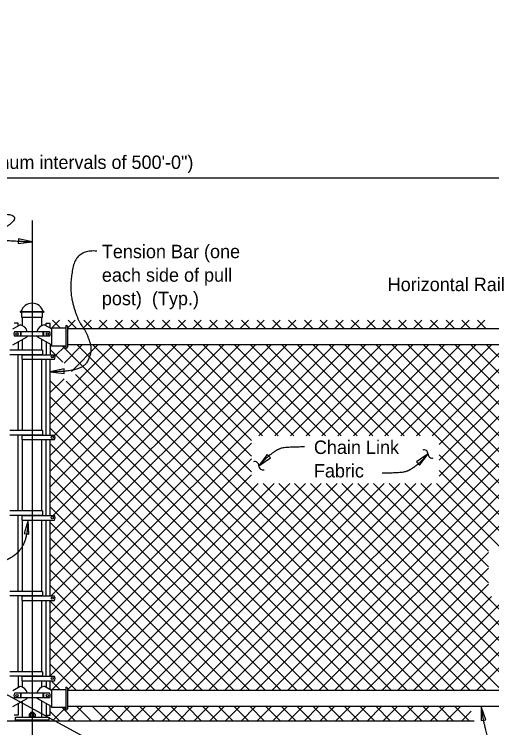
# Model space of a CAD drawing. Extents: x 110698 to 110915, y 110390 to 110472.
# Drawn here: x 110786.56 to 110793.7, y 110413.66 to 110424.35 of the extents above; entities that cross this region are included whole.
import ezdxf

# ---------------------------------------------------------------- set-up
doc = ezdxf.new("R2010")
doc.units = 0
for name, color, linetype in [('AdhocPoint_dp', 7, 'Continuous'), ('Border', 7, 'Continuous'), ('PlotBorder_dp', 7, 'Continuous'), ('SheetBorder_dp', 7, 'Continuous'), ('SheetLines_dp', 7, 'Continuous'), ('TextMisc', 7, 'Continuous')]:
    doc.layers.add(name, color=color, linetype=linetype)

msp = doc.modelspace()

# ---------------------------------------------------------------- linework, layer by layer
at = {"layer": 'AdhocPoint_dp'}
msp.add_line((110786.826, 110421.264), (110786.826, 110413.354), dxfattribs=at)
at = {"layer": 'PlotBorder_dp'}
for p, q in [((110776.826, 110421.899), (110796.826, 110421.899)), ((110786.826, 110413.828), (110786.826, 110413.827))]:
    msp.add_line(p, q, dxfattribs=at)
for points in [[(110786.826, 110420.942), (110786.62, 110420.989), (110786.616, 110420.919)], [(110787.096, 110418.997), (110787.306, 110418.971), (110787.303, 110419.041)], [(110792.751, 110417.764), (110792.576, 110417.646), (110792.625, 110417.595)], [(110790.219, 110417.588), (110790.394, 110417.706), (110790.346, 110417.757)], [(110786.768, 110416.774), (110786.708, 110416.572), (110786.778, 110416.563)], [(110793.547, 110413.981), (110793.548, 110413.77), (110793.618, 110413.783)]]:
    msp.add_lwpolyline(points, close=True, dxfattribs=at)
for centre, start, end in [((110792.691, 110417.766), 357.7178, 109.445), ((110792.81, 110417.762), 177.7178, 289.445), ((110790.16, 110417.59), 357.7178, 109.445), ((110790.279, 110417.585), 177.7178, 289.445)]:
    msp.add_arc(centre, 0.0596, start, end, dxfattribs=at)
for points in [[(110785.936, 110421.366), (110786.482, 110421.376), (110786.604, 110421.287), (110786.36, 110421.106), (110786.275, 110421.087), (110786.275, 110420.97), (110786.553, 110420.957), (110786.826, 110420.942)], [(110787.792, 110420.802), (110787.492, 110420.834), (110787.376, 110420.252), (110787.492, 110419.797), (110787.655, 110419.562), (110787.734, 110419.276), (110787.548, 110418.987), (110787.096, 110418.997)], [(110790.904, 110417.869), (110790.614, 110417.869), (110790.478, 110417.824), (110790.291, 110417.671), (110790.252, 110417.613)], [(110792.066, 110417.482), (110792.356, 110417.482), (110792.493, 110417.527), (110792.68, 110417.68), (110792.718, 110417.738)], [(110785.137, 110416.179), (110785.534, 110416.185), (110785.983, 110416.122), (110786.344, 110416.105), (110786.765, 110416.383), (110786.768, 110416.774)], [(110793.235, 110413.234), (110793.458, 110413.231), (110793.543, 110413.27), (110793.674, 110413.419), (110793.589, 110413.716), (110793.547, 110413.981)]]:
    msp.add_open_spline(points, degree=2, dxfattribs=at)
at = {"layer": 'SheetBorder_dp'}
for p, q in [((110787.122, 110419.653), (110787.237, 110419.768)), ((110787.129, 110419.768), (110787.244, 110419.653)), ((110787.355, 110419.651), (110787.472, 110419.768)), ((110787.365, 110419.768), (110787.495, 110419.638)), ((110787.578, 110419.638), (110787.708, 110419.768)), ((110787.6, 110419.768), (110787.731, 110419.638)), ((110787.813, 110419.638), (110787.944, 110419.768)), ((110787.836, 110419.768), (110787.966, 110419.638)), ((110788.049, 110419.638), (110788.179, 110419.768)), ((110788.072, 110419.768), (110788.202, 110419.638)), ((110788.285, 110419.638), (110788.415, 110419.768)), ((110788.308, 110419.768), (110788.438, 110419.638)), ((110788.521, 110419.638), (110788.651, 110419.768)), ((110788.543, 110419.768), (110788.673, 110419.638)), ((110788.756, 110419.638), (110788.886, 110419.768)), ((110788.779, 110419.768), (110788.909, 110419.638)), ((110788.992, 110419.638), (110789.122, 110419.768)), ((110789.015, 110419.768), (110789.145, 110419.638)), ((110789.228, 110419.638), (110789.358, 110419.768)), ((110789.25, 110419.768), (110789.381, 110419.638)), ((110789.463, 110419.638), (110789.594, 110419.768)), ((110789.486, 110419.768), (110789.616, 110419.638)), ((110789.699, 110419.638), (110789.829, 110419.768)), ((110789.722, 110419.768), (110789.852, 110419.638)), ((110789.935, 110419.638), (110790.065, 110419.768)), ((110789.958, 110419.768), (110790.088, 110419.638)), ((110790.17, 110419.638), (110790.301, 110419.768)), ((110790.193, 110419.768), (110790.323, 110419.638)), ((110790.406, 110419.638), (110790.536, 110419.768)), ((110790.429, 110419.768), (110790.559, 110419.638)), ((110790.642, 110419.638), (110790.772, 110419.768)), ((110790.665, 110419.768), (110790.795, 110419.638)), ((110790.878, 110419.638), (110791.008, 110419.768)), ((110790.9, 110419.768), (110791.03, 110419.638)), ((110791.113, 110419.638), (110791.243, 110419.768)), ((110791.136, 110419.768), (110791.266, 110419.638)), ((110791.349, 110419.638), (110791.479, 110419.768)), ((110791.372, 110419.768), (110791.502, 110419.638)), ((110791.585, 110419.638), (110791.715, 110419.768)), ((110791.607, 110419.768), (110791.738, 110419.638)), ((110791.82, 110419.638), (110791.951, 110419.768)), ((110791.843, 110419.768), (110791.973, 110419.638)), ((110792.056, 110419.638), (110792.186, 110419.768)), ((110792.079, 110419.768), (110792.209, 110419.638)), ((110792.292, 110419.638), (110792.422, 110419.768)), ((110792.315, 110419.768), (110792.445, 110419.638)), ((110792.528, 110419.638), (110792.658, 110419.768)), ((110792.55, 110419.768), (110792.68, 110419.638)), ((110792.763, 110419.638), (110792.893, 110419.768)), ((110792.786, 110419.768), (110792.916, 110419.638)), ((110792.999, 110419.638), (110793.129, 110419.768)), ((110793.022, 110419.768), (110793.152, 110419.638)), ((110793.235, 110419.638), (110793.365, 110419.768)), ((110793.257, 110419.768), (110793.388, 110419.638)), ((110793.47, 110419.638), (110793.6, 110419.768)), ((110793.493, 110419.768), (110793.623, 110419.638)), ((110787.096, 110416.328), (110790.167, 110419.398)), ((110787.096, 110415.857), (110790.638, 110419.398)), ((110787.096, 110417.742), (110788.752, 110419.398)), ((110787.096, 110417.271), (110789.224, 110419.398)), ((110787.096, 110418.214), (110788.281, 110419.398)), ((110787.096, 110416.092), (110790.402, 110419.398)), ((110787.096, 110416.564), (110789.931, 110419.398)), ((110787.096, 110417.035), (110789.46, 110419.398)), ((110787.096, 110417.506), (110788.988, 110419.398)), ((110787.096, 110415.149), (110791.345, 110419.398)), ((110787.096, 110415.385), (110791.109, 110419.398)), ((110787.096, 110418.449), (110788.045, 110419.398)), ((110787.113, 110415.637), (110790.874, 110419.398)), ((110787.139, 110416.842), (110789.695, 110419.398)), ((110787.162, 110418.044), (110788.517, 110419.398)), ((110787.168, 110419.228), (110787.328, 110419.388)), ((110787.28, 110419.381), (110792.44, 110414.221)), ((110787.303, 110419.127), (110787.574, 110419.398)), ((110787.414, 110419.002), (110787.81, 110419.398)), ((110787.499, 110419.398), (110792.676, 110414.221)), ((110787.735, 110419.398), (110792.912, 110414.221)), ((110787.97, 110419.398), (110793.147, 110414.221)), ((110788.206, 110419.398), (110790.108, 110417.496)), ((110788.442, 110419.398), (110790.108, 110417.732)), ((110788.677, 110419.398), (110790.108, 110417.967)), ((110788.913, 110419.398), (110790.274, 110418.038)), ((110789.149, 110419.398), (110790.509, 110418.038)), ((110789.384, 110419.398), (110790.745, 110418.038)), ((110789.62, 110419.398), (110790.981, 110418.038)), ((110789.856, 110419.398), (110791.216, 110418.038)), ((110789.939, 110414.221), (110795.116, 110419.398)), ((110790.092, 110419.398), (110791.452, 110418.038)), ((110790.175, 110414.221), (110795.352, 110419.398)), ((110790.22, 110418.038), (110791.581, 110419.398)), ((110790.327, 110419.398), (110791.688, 110418.038)), ((110790.411, 110414.221), (110795.588, 110419.398)), ((110790.456, 110418.038), (110791.817, 110419.398)), ((110790.563, 110419.398), (110791.923, 110418.038)), ((110790.646, 110414.221), (110795.823, 110419.398)), ((110790.692, 110418.038), (110792.052, 110419.398)), ((110790.799, 110419.398), (110792.159, 110418.038)), ((110790.882, 110414.221), (110796.059, 110419.398)), ((110790.927, 110418.038), (110792.288, 110419.398)), ((110791.034, 110419.398), (110792.395, 110418.038)), ((110791.118, 110414.221), (110796.296, 110419.399)), ((110791.163, 110418.038), (110792.524, 110419.398)), ((110791.27, 110419.398), (110792.631, 110418.038)), ((110791.353, 110414.221), (110796.513, 110419.381)), ((110791.399, 110418.038), (110792.759, 110419.398)), ((110791.506, 110419.398), (110794.532, 110416.372)), ((110791.635, 110418.038), (110792.995, 110419.398)), ((110791.741, 110419.398), (110794.767, 110416.372)), ((110791.87, 110418.038), (110793.231, 110419.398)), ((110791.977, 110419.398), (110795.003, 110416.372)), ((110792.106, 110418.038), (110793.466, 110419.398)), ((110792.213, 110419.398), (110795.239, 110416.372)), ((110792.342, 110418.038), (110793.702, 110419.398)), ((110792.449, 110419.398), (110795.474, 110416.372)), ((110792.577, 110418.038), (110793.938, 110419.398)), ((110792.684, 110419.398), (110795.71, 110416.372)), ((110792.813, 110418.038), (110794.174, 110419.398)), ((110792.916, 110417.905), (110794.409, 110419.398)), ((110792.916, 110417.434), (110794.881, 110419.398)), ((110792.916, 110417.669), (110794.645, 110419.398)), ((110792.92, 110419.398), (110795.946, 110416.372)), ((110793.156, 110419.398), (110796.182, 110416.372)), ((110793.391, 110419.398), (110796.417, 110416.372)), ((110793.627, 110419.398), (110796.68, 110416.346)), ((110787.096, 110419.329), (110787.285, 110419.141)), ((110787.473, 110418.953), (110792.205, 110414.221)), ((110787.096, 110418.685), (110787.303, 110418.892)), ((110787.096, 110418.858), (110791.733, 110414.221)), ((110787.336, 110418.854), (110791.969, 110414.221)), ((110787.096, 110418.622), (110791.497, 110414.221)), ((110787.096, 110418.386), (110791.262, 110414.221)), ((110787.096, 110418.151), (110791.026, 110414.221)), ((110787.096, 110414.914), (110790.108, 110417.925)), ((110787.096, 110417.915), (110790.79, 110414.221)), ((110787.096, 110414.678), (110790.108, 110417.69)), ((110787.096, 110417.679), (110790.555, 110414.221)), ((110792.916, 110417.752), (110794.296, 110416.372)), ((110787.096, 110414.442), (110790.108, 110417.454)), ((110787.096, 110417.444), (110790.319, 110414.221)), ((110792.916, 110417.516), (110794.06, 110416.372)), ((110787.126, 110414.236), (110790.21, 110417.32)), ((110787.355, 110414.229), (110790.446, 110417.32)), ((110787.582, 110414.221), (110790.681, 110417.32)), ((110787.818, 110414.221), (110790.917, 110417.32)), ((110788.054, 110414.221), (110791.153, 110417.32)), ((110788.289, 110414.221), (110791.389, 110417.32)), ((110788.525, 110414.221), (110791.624, 110417.32)), ((110788.761, 110414.221), (110791.86, 110417.32)), ((110788.996, 110414.221), (110792.096, 110417.32)), ((110789.232, 110414.221), (110792.331, 110417.32)), ((110789.468, 110414.221), (110792.567, 110417.32)), ((110789.704, 110414.221), (110792.803, 110417.32)), ((110790.284, 110417.32), (110793.383, 110414.221)), ((110790.52, 110417.32), (110793.619, 110414.221)), ((110790.755, 110417.32), (110793.854, 110414.221)), ((110790.991, 110417.32), (110794.09, 110414.221)), ((110791.227, 110417.32), (110794.326, 110414.221)), ((110791.462, 110417.32), (110794.562, 110414.221)), ((110791.698, 110417.32), (110794.797, 110414.221)), ((110791.934, 110417.32), (110795.033, 110414.221)), ((110792.169, 110417.32), (110793.655, 110415.835)), ((110792.405, 110417.32), (110793.655, 110416.071)), ((110792.641, 110417.32), (110793.655, 110416.306)), ((110792.877, 110417.32), (110793.825, 110416.372)), ((110787.096, 110417.208), (110790.083, 110414.221)), ((110787.096, 110416.972), (110789.848, 110414.221)), ((110787.096, 110416.736), (110789.612, 110414.221)), ((110787.096, 110416.501), (110789.376, 110414.221)), ((110791.589, 110414.221), (110793.655, 110416.287)), ((110787.096, 110416.265), (110789.14, 110414.221)), ((110787.096, 110416.029), (110788.905, 110414.221)), ((110791.825, 110414.221), (110793.655, 110416.051)), ((110787.096, 110415.794), (110788.669, 110414.221)), ((110792.061, 110414.221), (110793.655, 110415.815)), ((110792.296, 110414.221), (110793.702, 110415.627)), ((110792.532, 110414.221), (110793.938, 110415.627)), ((110792.768, 110414.221), (110794.173, 110415.627)), ((110793.003, 110414.221), (110794.409, 110415.627)), ((110793.239, 110414.221), (110794.645, 110415.627)), ((110793.475, 110414.221), (110794.88, 110415.627)), ((110787.096, 110415.558), (110788.433, 110414.221)), ((110787.096, 110415.322), (110788.198, 110414.221)), ((110787.096, 110415.087), (110787.962, 110414.221)), ((110787.096, 110414.851), (110787.726, 110414.221)), ((110787.096, 110414.615), (110787.491, 110414.221)), ((110787.111, 110414.365), (110787.239, 110414.236)), ((110787.129, 110413.768), (110787.328, 110413.967)), ((110787.276, 110413.964), (110787.472, 110413.768)), ((110787.365, 110413.768), (110787.578, 110413.981)), ((110787.494, 110413.981), (110787.708, 110413.768)), ((110787.73, 110413.981), (110787.944, 110413.768)), ((110787.836, 110413.768), (110788.05, 110413.981)), ((110787.966, 110413.981), (110788.179, 110413.768)), ((110788.072, 110413.768), (110788.285, 110413.981)), ((110788.202, 110413.981), (110788.415, 110413.768)), ((110788.308, 110413.768), (110788.521, 110413.981)), ((110788.437, 110413.981), (110788.651, 110413.768)), ((110788.543, 110413.768), (110788.757, 110413.981)), ((110788.673, 110413.981), (110788.886, 110413.768)), ((110788.779, 110413.768), (110788.993, 110413.981)), ((110788.909, 110413.981), (110789.122, 110413.768)), ((110789.015, 110413.768), (110789.228, 110413.981)), ((110789.144, 110413.981), (110789.358, 110413.768)), ((110789.25, 110413.768), (110789.464, 110413.981)), ((110789.38, 110413.981), (110789.594, 110413.768)), ((110789.486, 110413.768), (110789.7, 110413.981)), ((110789.616, 110413.981), (110789.829, 110413.768)), ((110789.722, 110413.768), (110789.935, 110413.981)), ((110789.851, 110413.981), (110790.065, 110413.768)), ((110789.958, 110413.768), (110790.171, 110413.981)), ((110790.087, 110413.981), (110790.301, 110413.768)), ((110790.193, 110413.768), (110790.407, 110413.981)), ((110790.323, 110413.981), (110790.536, 110413.768)), ((110790.429, 110413.768), (110790.642, 110413.981)), ((110790.559, 110413.981), (110790.772, 110413.768)), ((110790.665, 110413.768), (110790.878, 110413.981)), ((110790.794, 110413.981), (110791.008, 110413.768)), ((110790.9, 110413.768), (110791.114, 110413.981)), ((110791.03, 110413.981), (110791.243, 110413.768)), ((110791.136, 110413.768), (110791.35, 110413.981)), ((110791.266, 110413.981), (110791.479, 110413.768)), ((110791.372, 110413.768), (110791.585, 110413.981)), ((110791.501, 110413.981), (110791.715, 110413.768)), ((110791.607, 110413.768), (110791.821, 110413.981)), ((110791.737, 110413.981), (110791.951, 110413.768)), ((110791.843, 110413.768), (110792.057, 110413.981)), ((110791.973, 110413.981), (110792.186, 110413.768)), ((110792.079, 110413.768), (110792.292, 110413.981)), ((110792.208, 110413.981), (110792.422, 110413.768)), ((110792.315, 110413.768), (110792.528, 110413.981)), ((110792.444, 110413.981), (110792.658, 110413.768)), ((110792.55, 110413.768), (110792.764, 110413.981)), ((110792.68, 110413.981), (110792.893, 110413.768)), ((110792.786, 110413.768), (110792.999, 110413.981)), ((110792.916, 110413.981), (110793.129, 110413.768)), ((110793.022, 110413.768), (110793.235, 110413.981)), ((110793.151, 110413.981), (110793.365, 110413.768)), ((110786.814, 110413.889), (110786.835, 110413.889)), ((110786.814, 110413.88), (110786.835, 110413.88)), ((110787.096, 110413.908), (110787.237, 110413.768)), ((110793.257, 110413.768), (110793.398, 110413.909)), ((110786.576, 110413.775), (110787.076, 110413.775)), ((110786.576, 110413.771), (110787.076, 110413.771))]:
    msp.add_line(p, q, dxfattribs=at)
msp.add_lwpolyline([(110786.576, 110413.778), (110787.076, 110413.778), (110787.076, 110413.768), (110786.576, 110413.768)], close=True, dxfattribs=at)
at = {"layer": 'SheetLines_dp'}
for p, q in [((110767.724, 110424.352), (110816.333, 110397.889)), ((110780.282, 110413.768), (110793.44, 110413.768))]:
    msp.add_line(p, q, dxfattribs=at)
at = {"layer": 'TextMisc'}
for p, q in [((110786.653, 110419.9), (110786.998, 110419.9)), ((110786.998, 110419.888), (110786.653, 110419.888)), ((110786.672, 110419.808), (110786.672, 110419.888)), ((110786.98, 110419.808), (110786.672, 110419.808)), ((110786.68, 110419.688), (110786.68, 110419.808)), ((110786.971, 110419.688), (110786.971, 110419.808)), ((110786.98, 110419.808), (110786.98, 110419.888)), ((110786.536, 110419.638), (110786.647, 110419.7)), ((110786.617, 110419.726), (110786.555, 110419.726)), ((110786.617, 110419.683), (110786.617, 110419.726)), ((110787.115, 110419.638), (110787.004, 110419.7)), ((110787.034, 110419.685), (110787.034, 110419.726)), ((110787.034, 110419.726), (110787.096, 110419.726)), ((110787.096, 110419.649), (110787.096, 110419.726)), ((110787.088, 110419.596), (110786.563, 110419.596)), ((110786.646, 110419.588), (110786.669, 110419.588)), ((110787.006, 110419.588), (110786.982, 110419.588)), ((110787.115, 110419.653), (110787.115, 110419.381)), ((110787.115, 110419.653), (110787.328, 110419.653)), ((110787.328, 110419.673), (110787.328, 110419.363)), ((110787.355, 110419.673), (110787.355, 110419.363)), ((110796.296, 110419.638), (110787.355, 110419.638)), ((110786.536, 110419.399), (110786.75, 110419.518)), ((110787.088, 110419.528), (110786.563, 110419.528)), ((110786.646, 110419.578), (110786.669, 110419.578)), ((110786.646, 110419.568), (110786.669, 110419.568)), ((110786.646, 110419.556), (110786.669, 110419.556)), ((110786.646, 110419.544), (110786.669, 110419.544)), ((110786.646, 110419.534), (110786.669, 110419.534)), ((110786.68, 110419.319), (110786.68, 110419.479)), ((110787.115, 110419.399), (110786.901, 110419.518)), ((110786.971, 110419.319), (110786.971, 110419.479)), ((110787.006, 110419.578), (110786.982, 110419.578)), ((110787.006, 110419.568), (110786.982, 110419.568)), ((110787.006, 110419.556), (110786.982, 110419.556)), ((110787.006, 110419.544), (110786.982, 110419.544)), ((110787.006, 110419.534), (110786.982, 110419.534)), ((110786.617, 110419.444), (110786.617, 110419.319)), ((110787.034, 110419.444), (110787.034, 110419.251)), ((110787.034, 110419.444), (110787.034, 110419.397)), ((110787.096, 110419.409), (110787.096, 110419.251)), ((110787.096, 110419.409), (110787.096, 110419.397)), ((110787.328, 110419.381), (110787.115, 110419.381)), ((110796.296, 110419.398), (110787.355, 110419.398)), ((110786.981, 110419.319), (110786.49, 110419.319)), ((110786.981, 110419.319), (110786.981, 110419.251)), ((110786.981, 110419.251), (110786.491, 110419.251)), ((110786.617, 110418.114), (110786.617, 110419.251)), ((110786.67, 110419.251), (110786.67, 110419.184)), ((110786.67, 110419.251), (110787.161, 110419.251)), ((110786.67, 110419.184), (110787.16, 110419.184)), ((110786.68, 110418.114), (110786.68, 110419.184)), ((110786.971, 110418.114), (110786.971, 110419.184)), ((110787.034, 110418.047), (110787.034, 110419.184)), ((110787.096, 110418.047), (110787.096, 110419.184)), ((110786.981, 110418.114), (110786.49, 110418.114)), ((110786.981, 110418.114), (110786.981, 110418.047)), ((110786.981, 110418.047), (110786.491, 110418.047)), ((110786.617, 110416.91), (110786.617, 110418.047)), ((110786.67, 110418.047), (110786.67, 110417.979)), ((110786.67, 110418.047), (110787.161, 110418.047)), ((110786.67, 110417.979), (110787.16, 110417.979)), ((110786.68, 110416.91), (110786.68, 110417.979)), ((110786.971, 110416.91), (110786.971, 110417.979)), ((110787.034, 110416.842), (110787.034, 110417.979)), ((110787.096, 110416.842), (110787.096, 110417.979)), ((110786.981, 110416.91), (110786.49, 110416.91)), ((110786.981, 110416.91), (110786.981, 110416.842)), ((110786.981, 110416.842), (110786.491, 110416.842)), ((110786.617, 110415.705), (110786.617, 110416.842)), ((110786.67, 110416.842), (110786.67, 110416.774)), ((110786.67, 110416.842), (110787.161, 110416.842)), ((110786.67, 110416.774), (110787.16, 110416.774)), ((110786.68, 110415.705), (110786.68, 110416.774)), ((110786.971, 110415.705), (110786.971, 110416.774)), ((110787.034, 110415.637), (110787.034, 110416.774)), ((110787.096, 110415.637), (110787.096, 110416.774)), ((110786.981, 110415.705), (110786.49, 110415.705)), ((110786.981, 110415.637), (110786.491, 110415.637)), ((110786.617, 110414.5), (110786.617, 110415.637)), ((110786.67, 110415.637), (110786.67, 110415.57)), ((110786.67, 110415.637), (110787.161, 110415.637)), ((110786.981, 110415.705), (110786.981, 110415.637)), ((110786.67, 110415.57), (110787.16, 110415.57)), ((110786.68, 110414.5), (110786.68, 110415.57)), ((110786.971, 110414.5), (110786.971, 110415.57)), ((110787.034, 110414.433), (110787.034, 110415.57)), ((110787.096, 110414.433), (110787.096, 110415.57)), ((110786.981, 110414.5), (110786.49, 110414.5)), ((110786.981, 110414.5), (110786.981, 110414.433)), ((110786.981, 110414.433), (110786.491, 110414.433)), ((110786.617, 110414.433), (110786.617, 110414.267)), ((110786.67, 110414.433), (110786.67, 110414.365)), ((110786.67, 110414.433), (110787.161, 110414.433)), ((110786.67, 110414.365), (110787.16, 110414.365)), ((110786.68, 110414.271), (110786.68, 110414.365)), ((110786.971, 110414.271), (110786.971, 110414.365)), ((110787.034, 110414.365), (110787.034, 110414.267)), ((110787.096, 110414.232), (110787.096, 110414.365)), ((110786.536, 110414.222), (110786.647, 110414.283)), ((110787.115, 110414.222), (110787.004, 110414.283)), ((110787.115, 110414.236), (110787.115, 110413.964)), ((110787.115, 110414.236), (110787.328, 110414.236)), ((110787.328, 110414.256), (110787.328, 110413.946)), ((110787.355, 110414.256), (110787.355, 110413.946)), ((110787.088, 110414.179), (110786.563, 110414.179)), ((110786.646, 110414.171), (110786.669, 110414.171)), ((110786.646, 110414.162), (110786.669, 110414.162)), ((110786.646, 110414.151), (110786.669, 110414.151)), ((110786.646, 110414.139), (110786.669, 110414.139)), ((110787.006, 110414.171), (110786.982, 110414.171)), ((110787.006, 110414.162), (110786.982, 110414.162)), ((110787.006, 110414.151), (110786.982, 110414.151)), ((110787.006, 110414.139), (110786.982, 110414.139)), ((110796.296, 110414.221), (110787.355, 110414.221)), ((110786.536, 110413.982), (110786.75, 110414.101)), ((110787.088, 110414.111), (110786.563, 110414.111)), ((110786.617, 110414.027), (110786.617, 110413.851)), ((110786.646, 110414.127), (110786.669, 110414.127)), ((110786.646, 110414.118), (110786.669, 110414.118)), ((110786.68, 110413.82), (110786.68, 110414.062)), ((110787.115, 110413.982), (110786.901, 110414.101)), ((110786.971, 110413.82), (110786.971, 110414.062)), ((110787.006, 110414.127), (110786.982, 110414.127)), ((110787.006, 110414.118), (110786.982, 110414.118)), ((110787.034, 110414.027), (110787.034, 110413.851)), ((110787.096, 110413.851), (110787.096, 110413.993)), ((110787.328, 110413.964), (110787.115, 110413.964)), ((110796.296, 110413.981), (110787.355, 110413.981)), ((110786.617, 110413.851), (110786.555, 110413.851)), ((110786.776, 110413.827), (110786.776, 110413.82)), ((110786.776, 110413.827), (110786.875, 110413.827)), ((110786.78, 110413.865), (110786.78, 110413.827)), ((110786.871, 110413.827), (110786.78, 110413.827)), ((110786.86, 110413.873), (110786.791, 110413.873)), ((110786.809, 110413.894), (110786.8, 110413.885)), ((110786.8, 110413.885), (110786.8, 110413.873)), ((110786.8, 110413.885), (110786.851, 110413.885)), ((110786.803, 110413.865), (110786.803, 110413.827)), ((110786.809, 110413.894), (110786.84, 110413.894)), ((110786.84, 110413.894), (110786.851, 110413.885)), ((110786.848, 110413.865), (110786.848, 110413.827)), ((110786.851, 110413.885), (110786.851, 110413.873)), ((110786.871, 110413.865), (110786.871, 110413.827)), ((110786.875, 110413.827), (110786.875, 110413.82)), ((110787.034, 110413.851), (110787.096, 110413.851)), ((110786.706, 110413.778), (110786.945, 110413.778))]:
    msp.add_line(p, q, dxfattribs=at)
msp.add_lwpolyline([(110786.576, 110413.82), (110787.076, 110413.82), (110787.076, 110413.778), (110786.576, 110413.778)], close=True, dxfattribs=at)
for centre, radius, start, end in [((110786.653, 110419.894), 0.00613, 91.1647, 268.8353), ((110786.998, 110419.894), 0.00613, 271.1647, 88.8353), ((110787.341, 110419.673), 0.0134, 0, 180), ((110787.341, 110419.363), 0.0134, 180, 0), ((110787.341, 110414.256), 0.0134, 0, 180), ((110787.341, 110413.946), 0.0134, 180, 0), ((110786.792, 110413.862), 0.0118, 16.5986, 164.7005), ((110786.826, 110413.839), 0.0347, 49.2015, 130.7985), ((110786.86, 110413.862), 0.0118, 15.1506, 163.5042)]:
    msp.add_arc(centre, radius, start, end, dxfattribs=at)
for centre, major_axis, start_param, end_param in [((110786.826, 110419.859), (0.171, 0), 0.252602, 2.888574), ((110786.612, 110419.564), (0.146, 0), 0.231126, 1.331255), ((110787.039, 110419.564), (-0.146, 0), 4.95193, 6.05206), ((110786.632, 110419.562), (-0.0776, 0), 5.810211, 6.75616), ((110787.019, 110419.562), (0.0776, 0), 5.810211, 6.75616), ((110786.612, 110419.564), (0.146, 0), 5.947976, 6.024627), ((110787.039, 110419.564), (-0.146, 0), 0.258558, 0.335209), ((110787.091, 110419.218), (0.0776, 0), 5.801244, 6.745158), ((110787.091, 110418.013), (0.0776, 0), 5.801046, 6.744962), ((110787.091, 110418.013), (0.0776, 0), 5.801046, 6.744962), ((110787.091, 110416.809), (0.0776, 0), 5.800848, 6.744767), ((110787.091, 110416.809), (0.0776, 0), 5.800848, 6.744767), ((110787.091, 110415.604), (0.0776, 0), 5.810211, 6.745158), ((110787.091, 110415.604), (0.0776, 0), 5.810211, 6.745158), ((110787.091, 110414.399), (0.0776, 0), 5.800651, 6.745353), ((110786.612, 110414.147), (0.146, 0), 0.231126, 1.331255), ((110787.039, 110414.147), (-0.146, 0), 4.95193, 6.05206), ((110786.632, 110414.145), (-0.0776, 0), 5.810211, 6.75616), ((110787.019, 110414.145), (0.0776, 0), 5.810211, 6.75616), ((110786.612, 110414.147), (0.146, 0), 5.947976, 6.024627), ((110787.039, 110414.147), (-0.146, 0), 0.258558, 0.335209)]:
    msp.add_ellipse(centre, major_axis=major_axis, ratio=0.957868, start_param=start_param, end_param=end_param, dxfattribs=at)
for centre, major_axis in [((110786.599, 110419.561), (0.0178, 0)), ((110787.052, 110419.561), (-0.0178, 0)), ((110787.127, 110419.219), (-0.0177, 0)), ((110787.127, 110418.014), (-0.0177, 0)), ((110787.127, 110418.014), (-0.0177, 0)), ((110787.127, 110416.809), (-0.0177, 0)), ((110787.127, 110416.809), (-0.0177, 0)), ((110787.127, 110415.604), (-0.0177, 0)), ((110787.127, 110415.604), (-0.0177, 0)), ((110787.127, 110414.4), (-0.0177, 0)), ((110786.599, 110414.145), (0.0178, 0)), ((110787.052, 110414.145), (-0.0178, 0))]:
    msp.add_ellipse(centre, major_axis=major_axis, ratio=0.957868, dxfattribs=at)

# ---------------------------------------------------------------- texts
at = {"layer": 'Border'}
for s, p in [('Pull Post Assembly (required at maximum intervals of 500\'-0")', (110781.856, 110422.034)), ('Horizontal Rail', (110792.147, 110420.204))]:
    msp.add_text(s, height=0.2016, dxfattribs=at).set_placement(p)
at = {"layer": 'PlotBorder_dp'}
for s, p in [('Tension Bar (one ', (110787.87, 110420.697)), ('each side of pull ', (110787.87, 110420.345)), ('post)  (Typ.)', (110787.87, 110419.993)), ('Chain Link ', (110791.043, 110417.764)), ('Fabric ', (110791.043, 110417.412))]:
    msp.add_text(s, height=0.2016, dxfattribs=at).set_placement(p)

doc.saveas('drawing.dxf')
